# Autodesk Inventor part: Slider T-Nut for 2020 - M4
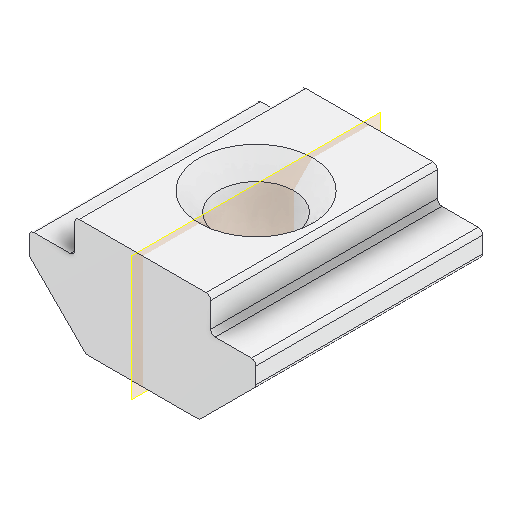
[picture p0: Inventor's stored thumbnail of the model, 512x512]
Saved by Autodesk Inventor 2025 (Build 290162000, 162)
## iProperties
Created: 2018-12
Part Number: Slider T-Nut for 2020 - M4
Material: Steel
Document SubType Name: Modeling
Designer: 18907419
Density: 7.85 g/cm^3
Appearance: Default
Sending System: Autodesk Translation Framework v7.6.0.251
Preprocessor: ST-DEVELOPER v17.2
Title: /Users/nikolaj/Library/Mobile Documents/com~apple~CloudDocs/3D printer/Mit byg/GrabCAD/T-Nut/Slider T-Nut for 2020 - M4.step
Author: nikolaj_tc@msn.com
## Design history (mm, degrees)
node "Body1"
node "Piano di lavoro1"
node "Solido1"
